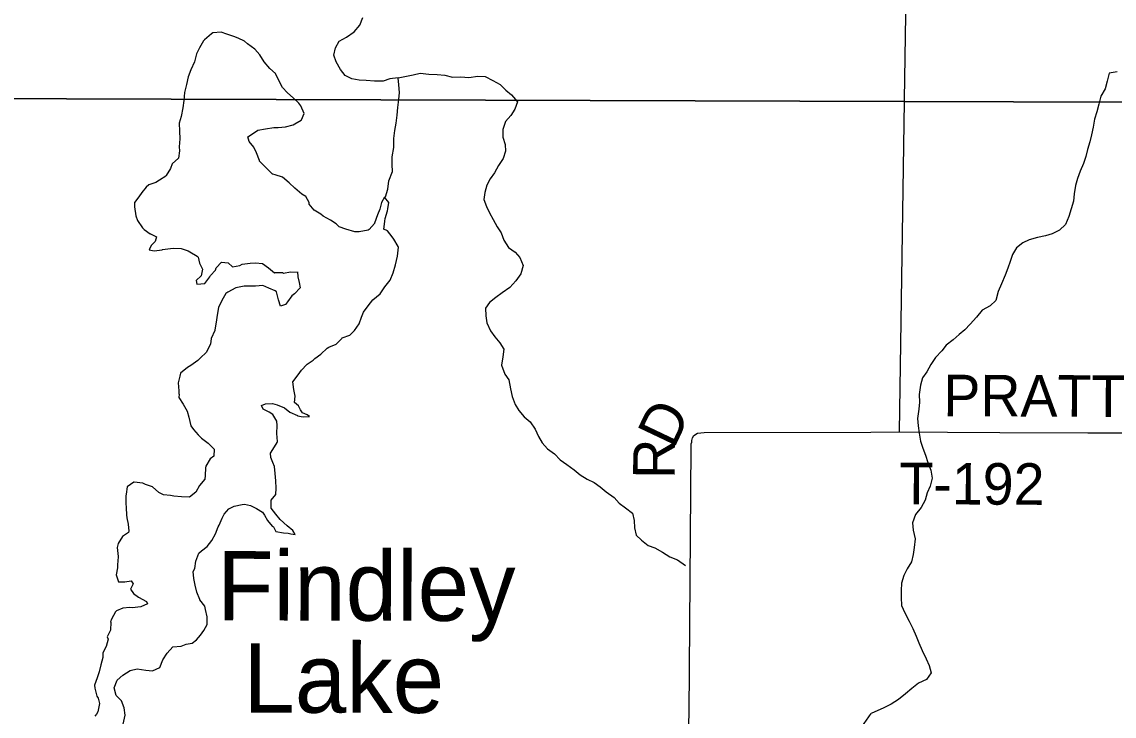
# Model space of a CAD drawing. Extents: x 1857828 to 2277390, y 930619 to 1324581.
# Drawn here: x 2046352 to 2054244, y 1138513 to 1143527 of the extents above; entities that cross this region are included whole.
import ezdxf

# ---------------------------------------------------------------- set-up
doc = ezdxf.new("R2010")
doc.units = 0
for name, color, linetype in [('GM_X_Major_Lake', 7, 'Continuous'), ('GM_X_Major_Lake_Text', 7, 'Continuous'), ('GM_X_Major_River', 7, 'Continuous'), ('GM_X_Minor_River', 7, 'Continuous'), ('GM_X_Township', 7, 'Continuous'), ('GM_X_Township_Road', 7, 'Continuous'), ('GM_X_Township_Road_Text', 7, 'Continuous')]:
    doc.layers.add(name, color=color, linetype=linetype)

msp = doc.modelspace()

# ---------------------------------------------------------------- linework, layer by layer
at = {"layer": 'GM_X_Major_Lake'}
for points in [[(2047961.6, 1143387), (2047915.1, 1143408.6), (2047882.8, 1143422.3), (2047832.4, 1143437.8), (2047792, 1143451.4), (2047731.8, 1143446.8), (2047721.8, 1143440.6), (2047672, 1143398), (2047664.1, 1143389.9), (2047636.5, 1143339.4), (2047612.9, 1143295), (2047599.5, 1143238.7), (2047574, 1143180.2), (2047554.5, 1143129.9), (2047541, 1143073.5), (2047527.6, 1143017.2), (2047522.2, 1142959), (2047514.7, 1142906.7), (2047503.4, 1142844.4), (2047489.9, 1142796.1), (2047490.5, 1142737.9), (2047493.1, 1142681.8), (2047489.8, 1142625.5), (2047492.1, 1142595.4), (2047484.7, 1142543.2)], [(2048350.9, 1140754.4), (2048322.4, 1140778.2), (2048325.9, 1140824.3), (2048317.4, 1140872.4), (2048310.7, 1140928.5), (2048348.4, 1140977.1), (2048372.1, 1141011.4), (2048370.1, 1141009.4), (2048413.8, 1141056), (2048457.7, 1141084.6), (2048469.6, 1141096.7), (2048513.5, 1141127.3), (2048557.2, 1141169.9), (2048571.2, 1141178.1), (2048623.2, 1141198.7), (2048665, 1141241.3), (2048666.9, 1141245.3), (2048723, 1141263.9), (2048754.8, 1141298.4), (2048790.4, 1141346.9), (2048805.9, 1141395.2), (2048819.6, 1141429.5), (2048855.3, 1141476), (2048886.9, 1141520.5), (2048940.7, 1141563.2), (2048974.3, 1141613.7), (2049014, 1141662.3), (2049014, 1141662.3), (2049035.5, 1141714.7), (2049052.9, 1141773.1), (2049066.3, 1141835.4), (2049073.6, 1141899.7), (2049071.5, 1141905.7), (2049040.8, 1141957.5), (2049028.6, 1141973.5), (2048993.9, 1142017.2), (2048967.7, 1142029), (2048975, 1142087.3), (2048976.8, 1142107.4), (2048994.3, 1142161.7), (2048996.2, 1142175.8), (2049003.7, 1142222), (2048973.1, 1142261.8), (2048951.4, 1142223.5), (2048937.9, 1142175.2), (2048922.3, 1142132.9), (2048900.8, 1142072.5), (2048898.9, 1142070.4), (2048861.1, 1142027.9), (2048853.2, 1142021.8), (2048789, 1142011.1), (2048756.8, 1142010.8), (2048692.3, 1142030.1), (2048643.9, 1142047.7), (2048623.5, 1142067.6), (2048581, 1142095.2), (2048530.4, 1142124.8), (2048512.2, 1142138.6), (2048463.6, 1142168.2), (2048429, 1142210), (2048428.9, 1142222), (2048404.3, 1142265.9), (2048373.9, 1142283.6), (2048325.2, 1142325.3), (2048282.6, 1142365), (2048235.9, 1142404.6), (2048183.4, 1142422.1), (2048165.3, 1142425.9), (2048163.3, 1142425.9), (2048112.5, 1142477.6), (2048069.8, 1142521.2), (2048069.7, 1142525.3), (2048047, 1142581.2), (2048028.4, 1142623.1), (2047993.8, 1142662.9), (2047985.4, 1142696.9), (2048033.3, 1142727.6), (2048057.2, 1142745.8), (2048111.4, 1142754.4), (2048173.6, 1142763.1), (2048203.7, 1142763.4), (2048255.9, 1142770), (2048312, 1142782.6), (2048324, 1142790.8), (2048369.9, 1142817.4), (2048371.9, 1142819.4), (2048391.5, 1142865.8), (2048368.8, 1142921.7), (2048352.5, 1142939.6), (2048311.9, 1142977.3), (2048271.2, 1143015), (2048234.6, 1143052.7), (2048208, 1143102.6), (2048185.3, 1143154.5), (2048142.7, 1143190.2), (2048103.9, 1143238), (2048071.2, 1143289.8), (2048036.6, 1143329.6), (2047981.9, 1143369.1), (2047961.6, 1143387)], [(2048350.9, 1140754.4), (2048322.4, 1140778.2), (2048325.9, 1140824.3), (2048317.4, 1140872.4), (2048310.7, 1140928.5), (2048348.4, 1140977.1), (2048372.1, 1141011.4), (2048370.1, 1141009.4), (2048413.8, 1141056), (2048457.7, 1141084.6), (2048469.6, 1141096.7), (2048513.5, 1141127.3), (2048557.2, 1141169.9), (2048571.2, 1141178.1), (2048623.2, 1141198.7), (2048665, 1141241.3), (2048666.9, 1141245.3), (2048723, 1141263.9), (2048754.8, 1141298.4), (2048790.4, 1141346.9), (2048805.9, 1141395.2), (2048819.6, 1141429.5), (2048855.3, 1141476), (2048886.9, 1141520.5), (2048940.7, 1141563.2), (2048974.3, 1141613.7), (2049014, 1141662.3), (2049014, 1141662.3), (2049035.5, 1141714.7), (2049052.9, 1141773.1), (2049066.3, 1141835.4), (2049073.6, 1141899.7), (2049071.5, 1141905.7), (2049040.8, 1141957.5), (2049028.6, 1141973.5), (2048993.9, 1142017.2), (2048967.7, 1142029), (2048967.7, 1142027), (2048975, 1142087.3), (2048976.8, 1142107.4), (2048994.3, 1142161.7), (2048996.2, 1142175.8), (2049003.7, 1142222), (2048973.1, 1142261.8), (2048951.4, 1142223.5), (2048937.9, 1142175.2), (2048922.3, 1142132.9), (2048900.8, 1142072.5), (2048898.9, 1142070.4), (2048861.1, 1142027.9), (2048853.2, 1142021.8), (2048789, 1142011.1), (2048756.8, 1142010.8), (2048692.3, 1142030.1), (2048643.9, 1142047.7), (2048623.5, 1142067.6), (2048581, 1142095.2), (2048530.4, 1142124.8), (2048512.2, 1142138.6), (2048463.6, 1142168.2), (2048429, 1142210), (2048428.9, 1142222), (2048404.3, 1142265.9), (2048373.9, 1142283.6), (2048325.2, 1142325.3), (2048282.6, 1142365), (2048235.9, 1142404.6), (2048183.4, 1142422.1), (2048165.3, 1142425.9), (2048163.3, 1142425.9), (2048112.5, 1142477.6), (2048069.8, 1142521.2), (2048069.7, 1142525.3), (2048047, 1142581.2), (2048028.4, 1142623.1), (2047993.8, 1142662.9), (2047985.4, 1142696.9), (2048033.3, 1142727.6), (2048057.2, 1142745.8), (2048111.4, 1142754.4), (2048173.6, 1142763.1), (2048203.7, 1142763.4), (2048255.9, 1142770), (2048312, 1142782.6), (2048324, 1142790.8), (2048369.9, 1142817.4), (2048371.9, 1142819.4), (2048391.5, 1142865.8), (2048368.8, 1142921.7), (2048352.5, 1142939.6), (2048311.9, 1142977.3), (2048271.2, 1143015), (2048234.6, 1143052.7), (2048208, 1143102.6), (2048185.3, 1143154.5), (2048142.7, 1143190.2), (2048103.9, 1143238), (2048071.2, 1143289.8), (2048036.6, 1143329.6), (2047981.9, 1143369.1), (2047961.6, 1143387)], [(2047484.7, 1142543.2), (2047438.9, 1142500.6), (2047427.2, 1142468.3), (2047395.6, 1142417.9), (2047393.7, 1142411.8), (2047345.8, 1142383.2), (2047319.8, 1142366.9), (2047269.8, 1142350.3), (2047249.8, 1142334.1), (2047220.1, 1142293.6), (2047196.4, 1142263.3), (2047166.7, 1142222.8), (2047165, 1142190.7), (2047175.8, 1142126.6), (2047188.2, 1142092.6), (2047223, 1142038.8), (2047235.2, 1142026.9), (2047279.7, 1141997.3), (2047281.8, 1141995.3), (2047326.2, 1141973.7), (2047316.5, 1141941.5), (2047286.7, 1141911.1), (2047273, 1141880.8), (2047309.3, 1141873.2), (2047365.5, 1141881.8), (2047367.4, 1141883.8), (2047425.6, 1141890.4), (2047447.7, 1141892.7), (2047504, 1141889.3), (2047554.5, 1141873.7), (2047566.6, 1141865.8), (2047619.2, 1141834.3), (2047627.3, 1141828.3), (2047635.9, 1141784.3), (2047658.5, 1141740.4), (2047646.9, 1141694.1), (2047611.1, 1141659.6), (2047617.4, 1141633.6), (2047673.7, 1141638.2), (2047709.3, 1141686.7), (2047715.2, 1141694.8), (2047751, 1141733.3), (2047756.8, 1141751.4), (2047794.6, 1141792), (2047842.9, 1141786.5), (2047875.3, 1141758.7), (2047927.5, 1141767.3), (2047943.4, 1141777.5), (2048001.7, 1141784.1), (2048039.8, 1141786.5), (2048092.1, 1141781), (2048134.7, 1141751.4), (2048177.3, 1141715.7), (2048183.3, 1141715.8), (2048235.6, 1141716.3), (2048243.6, 1141712.4), (2048293.8, 1141720.9), (2048293.8, 1141720.9), (2048344, 1141719.5), (2048344, 1141721.5), (2048346.4, 1141685.4), (2048354.9, 1141645.3), (2048363.4, 1141607.3), (2048321.7, 1141562.7), (2048303.8, 1141548.5), (2048272.1, 1141506), (2048256.2, 1141485.8), (2048220.2, 1141473.4), (2048205.6, 1141519.4), (2048192.9, 1141577.4), (2048182.8, 1141585.3), (2048136.3, 1141604.9), (2048093.9, 1141622.5), (2048039.7, 1141618), (2047981.4, 1141619.3), (2047957.3, 1141619.1), (2047897.1, 1141606.4), (2047841.2, 1141575.8), (2047825.2, 1141565.5), (2047797.7, 1141515.1), (2047772.1, 1141464.7), (2047762.7, 1141408.4), (2047762.7, 1141408.4), (2047755.2, 1141358.1), (2047745.8, 1141303.8), (2047745.8, 1141297.8), (2047720.3, 1141241.4), (2047714.8, 1141199.2), (2047691.2, 1141154.8), (2047685.3, 1141140.7), (2047639.5, 1141098.1), (2047623.6, 1141081.8), (2047573.8, 1141045.2), (2047549.8, 1141030.9), (2047498, 1140990.2), (2047494.3, 1140968.1), (2047480.7, 1140919.8), (2047485.4, 1140863.7), (2047485.7, 1140839.6), (2047487.7, 1140837.6), (2047486, 1140813.5)], [(2047486, 1140813.5), (2047518.6, 1140765.7), (2047547.3, 1140715.8), (2047557.9, 1140671.8), (2047572.7, 1140609.8), (2047593, 1140583.9), (2047625.6, 1140544.1), (2047650, 1140520.3), (2047698.7, 1140484.7), (2047735.2, 1140448.9), (2047741.4, 1140441), (2047739.9, 1140390.8), (2047714, 1140370.4), (2047682.4, 1140317.9), (2047678.6, 1140305.9), (2047677.2, 1140251.7), (2047673.4, 1140225.5), (2047635.8, 1140179), (2047608.2, 1140130.6), (2047562.4, 1140093.9), (2047506, 1140097.4), (2047449.7, 1140100.8), (2047425.5, 1140106.6), (2047375.2, 1140112.1), (2047340.9, 1140127.8), (2047296.2, 1140169.4), (2047245.8, 1140186.9), (2047225.6, 1140194.8), (2047163.2, 1140204.1), (2047161.2, 1140204.1), (2047113.3, 1140169.5), (2047105.9, 1140117.2), (2047104, 1140105.2), (2047104.6, 1140051), (2047105, 1140016.9), (2047107.6, 1139966.8), (2047109.8, 1139944.7), (2047120.4, 1139900.7), (2047125, 1139848.6), (2047123.1, 1139838.5), (2047079.2, 1139810), (2047047.6, 1139759.5), (2047041.9, 1139731.3), (2047048.6, 1139667.2), (2047048.7, 1139663.2), (2047043.3, 1139606.9), (2047043.5, 1139584.8), (2047034, 1139534.6), (2047050.7, 1139482.6), (2047052.7, 1139482.6), (2047096.9, 1139483.1), (2047143, 1139491.6), (2047157.4, 1139467.7), (2047137.7, 1139431.3), (2047160.1, 1139399.5), (2047194.6, 1139371.7), (2047253.2, 1139342.2), (2047259.5, 1139324.2), (2047211.5, 1139303.7), (2047211.5, 1139303.7), (2047149.2, 1139295), (2047133.1, 1139298.8), (2047082.9, 1139294.3), (2047036.9, 1139273.8), (2047029, 1139267.7), (2046999.4, 1139213.2), (2046993.6, 1139195), (2046995.7, 1139191.1), (2046992.3, 1139134.8), (2046968.7, 1139086.4), (2046974.9, 1139070.4), (2046961.4, 1139016.1), (2046937.8, 1138971.7), (2046936.2, 1138937.6), (2046922.7, 1138883.3), (2046911.2, 1138833), (2046897.6, 1138790.7), (2046897.6, 1138790.7), (2046878.2, 1138736.3), (2046880.4, 1138716.3), (2046893.1, 1138658.2), (2046903.3, 1138644.3), (2046913.8, 1138604.3), (2046902.4, 1138543.9), (2046891.9, 1138528.3), (2046879.9, 1138512.7)], [(2047486, 1140813.5), (2047518.6, 1140765.7), (2047547.3, 1140715.8), (2047557.9, 1140671.8), (2047572.7, 1140609.8), (2047593, 1140583.9), (2047625.6, 1140544.1), (2047650, 1140520.3), (2047698.7, 1140484.7), (2047735.2, 1140448.9), (2047741.4, 1140441), (2047739.9, 1140390.8), (2047714, 1140370.4), (2047682.4, 1140317.9), (2047678.6, 1140305.9), (2047677.2, 1140251.7), (2047673.4, 1140225.5), (2047635.8, 1140179), (2047608.2, 1140130.6), (2047562.4, 1140093.9), (2047506, 1140097.4), (2047449.7, 1140100.8), (2047425.5, 1140106.6), (2047375.2, 1140112.1), (2047340.9, 1140127.8), (2047296.2, 1140169.4), (2047245.8, 1140186.9), (2047225.6, 1140194.8), (2047163.2, 1140204.1), (2047161.2, 1140204.1), (2047113.3, 1140169.5), (2047105.9, 1140117.2), (2047104, 1140105.2), (2047104.6, 1140051), (2047105, 1140016.9), (2047107.6, 1139966.8), (2047109.8, 1139944.7), (2047120.4, 1139900.7), (2047125, 1139848.6), (2047123.1, 1139838.5), (2047079.2, 1139810), (2047047.6, 1139759.5), (2047041.9, 1139731.3), (2047048.6, 1139667.2), (2047048.7, 1139663.2), (2047043.3, 1139606.9), (2047043.5, 1139584.8), (2047034, 1139534.6), (2047050.7, 1139482.6), (2047052.7, 1139482.6), (2047096.9, 1139483.1), (2047143, 1139491.6), (2047157.4, 1139467.7), (2047137.7, 1139431.3), (2047160.1, 1139399.5), (2047194.6, 1139371.7), (2047253.2, 1139342.2), (2047259.5, 1139324.2), (2047211.5, 1139303.7), (2047211.5, 1139303.7), (2047149.2, 1139295), (2047133.1, 1139298.8), (2047082.9, 1139294.3), (2047036.9, 1139273.8), (2047029, 1139267.7), (2046999.4, 1139213.2), (2046993.6, 1139195), (2046995.7, 1139191.1), (2046992.3, 1139134.8), (2046968.7, 1139086.4), (2046974.9, 1139070.4), (2046961.4, 1139016.1), (2046937.8, 1138971.7), (2046936.2, 1138937.6), (2046922.7, 1138883.3), (2046911.2, 1138833), (2046897.6, 1138790.7), (2046897.6, 1138790.7), (2046878.2, 1138736.3), (2046880.4, 1138716.3), (2046893.1, 1138658.2), (2046903.3, 1138644.3), (2046913.8, 1138604.3), (2046902.4, 1138543.9), (2046891.9, 1138528.3), (2046880.5, 1138513.5)], [(2047072.6, 1138402), (2047099.7, 1138519.9), (2047091, 1138574), (2047072.4, 1138624), (2047033.8, 1138661.7), (2047019.1, 1138717.7), (2047040.5, 1138774.1), (2047082.3, 1138808.7), (2047134.2, 1138843.4), (2047184.3, 1138853.9), (2047246.8, 1138844.5), (2047297, 1138841.1), (2047349, 1138865.7), (2047370.5, 1138920.1), (2047402.1, 1138968.6), (2047443.8, 1139013.1), (2047504.1, 1139019.8), (2047516.1, 1139023.9), (2047540.1, 1139034.2), (2047582.2, 1139040.7), (2047614.1, 1139065.1), (2047641.9, 1139097.5), (2047667.6, 1139131.9), (2047691.2, 1139176.3), (2047691.1, 1139184.3), (2047690.6, 1139230.4), (2047680, 1139282.5), (2047673.7, 1139306.5), (2047639, 1139354.3), (2047639, 1139356.3), (2047616.3, 1139408.3), (2047603.7, 1139458.3), (2047595, 1139508.4), (2047590.5, 1139558.5), (2047602.3, 1139580.7), (2047609.7, 1139632.9), (2047631.2, 1139689.3), (2047631.2, 1139691.3), (2047651.1, 1139707.6), (2047691, 1139738.1), (2047724.6, 1139780.6), (2047752.2, 1139829.1), (2047771.8, 1139881.4), (2047777.6, 1139893.5), (2047799.2, 1139941.9), (2047812.9, 1139972.2), (2047848.7, 1140010.7), (2047886.7, 1140029.1), (2047944.8, 1140041.8), (2047960.9, 1140043.9), (2048003.2, 1140034.4), (2048047.6, 1140012.8), (2048092.1, 1139987.1), (2048104.4, 1139965.2), (2048127, 1139927.3), (2048161.6, 1139885.5), (2048169.7, 1139879.6), (2048186.2, 1139845.7), (2048242.6, 1139836.2), (2048242.6, 1139836.2), (2048276.7, 1139834.6), (2048294.9, 1139830.7), (2048327.1, 1139825.1), (2048310.7, 1139853), (2048270.1, 1139888.7), (2048217.4, 1139932.3), (2048186.8, 1139972.1), (2048154.1, 1140015.9), (2048153.5, 1140074.1), (2048153.5, 1140074.1), (2048187.2, 1140114.6), (2048188.7, 1140160.7), (2048188.1, 1140212.9), (2048183.5, 1140265), (2048176.9, 1140317.1), (2048166.5, 1140345.1), (2048150, 1140381), (2048147.7, 1140413.1), (2048165.5, 1140439.4), (2048197, 1140489.9), (2048199, 1140495.9), (2048194.3, 1140554.1), (2048195.7, 1140612.3), (2048195.3, 1140644.4), (2048166.6, 1140692.2), (2048138.3, 1140708), (2048095.9, 1140729.6), (2048083.5, 1140755.6), (2048111.5, 1140767.9), (2048163.8, 1140770.5), (2048196, 1140760.8), (2048250.5, 1140739.3), (2048289, 1140709.6), (2048343.6, 1140684.1), (2048343.6, 1140682.1), (2048385.9, 1140674.5), (2048430.1, 1140676.9), (2048413.9, 1140688.8), (2048379.6, 1140702.5), (2048365.3, 1140724.4), (2048350.9, 1140754.4)]]:
    msp.add_lwpolyline(points, dxfattribs=at)
at = {"layer": 'GM_X_Major_River'}
msp.add_lwpolyline([(2048973.1, 1142261.8), (2048979.1, 1142263.9), (2048996.6, 1142318.3), (2049003.9, 1142378.6), (2049031.3, 1142447.1), (2049028.7, 1142497.2), (2049028.1, 1142553.4), (2049039.4, 1142619.7), (2049040.7, 1142683.9), (2049046.1, 1142742.2), (2049057.6, 1142794.5), (2049064.9, 1142852.8), (2049068.3, 1142909), (2049075.7, 1142965.2), (2049081.2, 1143017.5), (2049076.6, 1143071.6), (2049072, 1143121.7), (2049011.8, 1143115.1), (2048963.7, 1143098.5), (2048899.4, 1143097.8), (2048839, 1143103.2), (2048788.8, 1143104.7), (2048736.4, 1143116.2), (2048687.9, 1143139.8), (2048655.2, 1143183.6), (2048622.5, 1143239.4), (2048605.8, 1143287.4), (2048619.3, 1143339.7), (2048644.9, 1143388.1), (2048698.9, 1143416.8), (2048752.7, 1143455.5), (2048794.4, 1143504.1), (2048815.9, 1143558.5)], dxfattribs=at)
at = {"layer": 'GM_X_Minor_River'}
for points in [[(2049072, 1143121.6), (2049180.3, 1143144.9), (2049230.4, 1143155.5), (2049292.8, 1143148.1), (2049353.1, 1143146.7), (2049409.4, 1143141.3), (2049463.8, 1143127.8), (2049524.1, 1143130.4), (2049582.5, 1143125), (2049646.7, 1143133.8), (2049698.9, 1143132.3), (2049755.6, 1143102.8), (2049808.1, 1143075.2), (2049848.8, 1143033.5), (2049889.4, 1142999.8), (2049934.1, 1142950.1), (2049914.6, 1142895.8), (2049885, 1142851.3), (2049847.3, 1142806.8), (2049827.9, 1142748.4), (2049826.5, 1142694.2), (2049843.1, 1142642.2), (2049845.7, 1142592), (2049830.2, 1142539.7), (2049796.6, 1142489.2), (2049767, 1142436.7), (2049735.3, 1142394.2), (2049711.8, 1142347.8), (2049696.3, 1142295.5), (2049690.8, 1142245.3), (2049709.5, 1142193.3), (2049732.1, 1142147.4), (2049756.7, 1142099.5), (2049785.5, 1142047.6), (2049814.1, 1142003.8), (2049834.8, 1141949.8), (2049867.5, 1141898), (2049916.2, 1141864.4), (2049950.8, 1141824.6), (2049973.5, 1141766.7), (2049958.1, 1141706.3), (2049920.5, 1141655.8), (2049876.8, 1141609.1), (2049823, 1141570.4), (2049777.1, 1141535.8), (2049731.3, 1141499.2), (2049701.6, 1141458.8), (2049704.2, 1141404.6), (2049712.8, 1141354.6), (2049737.6, 1141296.6), (2049770.2, 1141252.8), (2049804.9, 1141209.1), (2049833.6, 1141163.2), (2049826.1, 1141109), (2049818.8, 1141048.7), (2049841.6, 1140982.7), (2049870.2, 1140940.9), (2049883, 1140876.8), (2049893.7, 1140822.7), (2049916.4, 1140764.8), (2049943, 1140720.9), (2049981.7, 1140675.1), (2050024.3, 1140639.5), (2050061.1, 1140585.7), (2050085.8, 1140531.8), (2050112.5, 1140487.9), (2050149.1, 1140444.1), (2050199.8, 1140406.6), (2050240.5, 1140364.8), (2050289.1, 1140331.2), (2050341.8, 1140291.7), (2050386.4, 1140256), (2050437, 1140224.4), (2050487.5, 1140200.9), (2050530.1, 1140169.2), (2050574.7, 1140133.6), (2050631.4, 1140092), (2050668.1, 1140052.3), (2050714.7, 1140018.6), (2050763.3, 1139979), (2050776, 1139927), (2050778.6, 1139872.8), (2050791.2, 1139820.8), (2050829.8, 1139783.1), (2050876.5, 1139745.4), (2050924.9, 1139727.9), (2050981.5, 1139698.4), (2051034.2, 1139662.8), (2051088.7, 1139641.3), (2051147.4, 1139601.8)], [(2054265.2, 1143166), (2054209, 1143157.4), (2054193.6, 1143099), (2054180.1, 1143042.7), (2054148.6, 1142990.2), (2054133.1, 1142931.8), (2054119.7, 1142877.5), (2054102.2, 1142823.1), (2054092.8, 1142766.9), (2054081.3, 1142710.6), (2054067.8, 1142660.2), (2054050.4, 1142605.9), (2054038.8, 1142555.6), (2054023.4, 1142503.3), (2053997.8, 1142448.8), (2053978.3, 1142396.5), (2053964.8, 1142344.1), (2053955.4, 1142285.8), (2053950, 1142231.6), (2053934.5, 1142177.3), (2053917.1, 1142120.9), (2053893.6, 1142064.5), (2053847.9, 1142021.9), (2053795.9, 1141997.2), (2053747.8, 1141980.7), (2053689.6, 1141970.1), (2053629.5, 1141953.4), (2053583.5, 1141930.8), (2053537.7, 1141896.2), (2053510.1, 1141847.8), (2053492.6, 1141797.4), (2053475, 1141749.1), (2053455.5, 1141696.7), (2053430.1, 1141636.2), (2053406.6, 1141579.8), (2053389.2, 1141515.4), (2053347.4, 1141476.9), (2053291.5, 1141446.2), (2053249.9, 1141395.6), (2053204.2, 1141342.9), (2053164.5, 1141302.4), (2053124.6, 1141269.9), (2053080.8, 1141231.3), (2053031, 1141192.6), (2052999.3, 1141152.2), (2052953.6, 1141103.6), (2052920, 1141053), (2052890.5, 1141000.6), (2052858.8, 1140956.1), (2052845.3, 1140903.8), (2052836, 1140835.4), (2052836.6, 1140781.3), (2052833.2, 1140729.1), (2052823.9, 1140662.8), (2052828.5, 1140610.6)], [(2052828.5, 1140610.6), (2052835.1, 1140556.5), (2052843.8, 1140498.4), (2052862.5, 1140448.4), (2052881.1, 1140398.5), (2052897.8, 1140344.5), (2052918.5, 1140290.5), (2052929.2, 1140232.4), (2052913.8, 1140174.1), (2052892.2, 1140125.7), (2052878.7, 1140073.4), (2052849.2, 1140020.9), (2052809.6, 1139968.3), (2052788.1, 1139909.9), (2052792.7, 1139855.8), (2052805.5, 1139793.7), (2052798.2, 1139731.4), (2052790.7, 1139681.2), (2052779.2, 1139628.9), (2052749.6, 1139576.4), (2052724.1, 1139528), (2052708.6, 1139473.6), (2052705.2, 1139421.4), (2052705.7, 1139369.3), (2052706.4, 1139313.1), (2052731.1, 1139259.2), (2052761.9, 1139199.3), (2052788.6, 1139145.4), (2052813.4, 1139091.5), (2052832, 1139043.5), (2052856.7, 1138987.6), (2052885.5, 1138927.7), (2052908.2, 1138879.8), (2052922.9, 1138825.8), (2052887.2, 1138777.2), (2052831.3, 1138750.6), (2052781.4, 1138711.9), (2052737.6, 1138675.3), (2052685.8, 1138634.6), (2052631.9, 1138600), (2052580, 1138573.3), (2052487.6, 1138532.9)], [(2052421.3, 1138436.6), (2052488.5, 1138531.8)]]:
    msp.add_lwpolyline(points, dxfattribs=at)
at = {"layer": 'GM_X_Township'}
msp.add_lwpolyline([(2059668.2, 1161839.2), (2059567.5, 1154416.5), (2059504.7, 1149211.4), (2059473.8, 1146652.1), (2059427, 1142930.1), (2056661.3, 1142938.9), (2052729.5, 1142952), (2045916.5, 1142974.4), (2040844, 1142991), (2037494.9, 1143002), (2032060.1, 1143019.8), (2032103, 1147062.7), (2032163.6, 1154605.4), (2032187.8, 1160111), (2032186.7, 1160189.2), (2032190.8, 1160393.7)], dxfattribs=at)
msp.add_lwpolyline([(2031808.5, 1116642.9), (2031829.7, 1118868.9), (2031879.9, 1124126.9), (2031935.7, 1129983.3), (2031982.7, 1134914.9), (2032027.6, 1139963.5), (2032060.1, 1143019.8), (2037494.9, 1143002), (2040844, 1142991), (2045916.5, 1142974.4), (2052729.5, 1142952), (2056661.3, 1142938.9), (2059427, 1142930.1), (2059329.7, 1135138.9), (2059259.3, 1129509), (2059186.4, 1123686.3), (2059120.2, 1118390.4), (2059091.9, 1116133.9), (2056316.7, 1116163.7), (2050782.4, 1116223.1), (2045569.8, 1116279), (2040306, 1116370), (2037470.7, 1116419.9), (2035129.3, 1116512.1)], close=True, dxfattribs=at)
at = {"layer": 'GM_X_Township_Road'}
for points in [[(2052729.7, 1142966.1), (2052789.4, 1146775.2)], [(2052692.1, 1140565.8), (2052729.5, 1142952), (2052729.7, 1142966.1), (2052729.7, 1142966.1)], [(2051070.8, 1135250.6), (2051173.2, 1138535.4), (2051188.1, 1140452.7), (2051188, 1140480.8), (2051191.9, 1140492.8), (2051193.9, 1140504.8), (2051197.8, 1140522.9), (2051207.8, 1140541), (2051233.8, 1140557.1), (2051282, 1140561.3), (2052485.5, 1140563.1), (2052692.1, 1140565.8)], [(2052692.1, 1140565.8), (2053039.2, 1140562.9), (2053418.3, 1140562.1), (2054054.3, 1140560.1), (2054710.2, 1140560.2), (2056633.3, 1140550.2)]]:
    msp.add_lwpolyline(points, dxfattribs=at)

# ---------------------------------------------------------------- texts
at = {"layer": 'GM_X_Major_Lake_Text'}
for s, rotation, p in [('Findley', 359.8787, (2047761.7, 1139205.1)), ('Lake', 359.87881, (2047952.4, 1138539.4))]:
    msp.add_text(s, height=500.22, rotation=rotation, dxfattribs=at).set_placement(p)
at = {"layer": 'GM_X_Township_Road_Text'}
for s, rotation, p in [('PRATT', 359.7827, (2053009.3, 1140679.2)), ('D', 64.64221, (2051062.5, 1140438.5)), ('R', 89.50433, (2051068, 1140225.4)), ('T-192', 359.71769, (2052692.1, 1140044.2))]:
    msp.add_text(s, height=300, rotation=rotation, dxfattribs=at).set_placement(p)

doc.saveas('drawing.dxf')
